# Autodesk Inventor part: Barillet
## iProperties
Shininess: 64.0
Length Units: 11269
Angle Units: 11279
Time Units: 11290
Mass Units: 11283
Length Display Precision: 3
Angle Display Precision: 2
Compacted: True
Part Number: Barillet
Document SubType Name: Modeling
Created: 2005-01
Material: Par défaut
Designer: Flavien MARTY
Density: 0.0
Volumn: 0.0
Area: 0.0
PropertySet Name: Model Information
Control State: 0
Master: False
Checked Out: False
Norme de conversion: STEP AP203
Nom du fichier: Barillet.STEP
Préprocesseur: SolidWorks 2001039
Postprocesseur: Build: Release: 6 RTM Build: 90b - Date: Tue 09/24/2002
Unités envoyées: MILLIMETERS
Incertitude: 0.0
Author: Flavien MARTY
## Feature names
1. Base1
